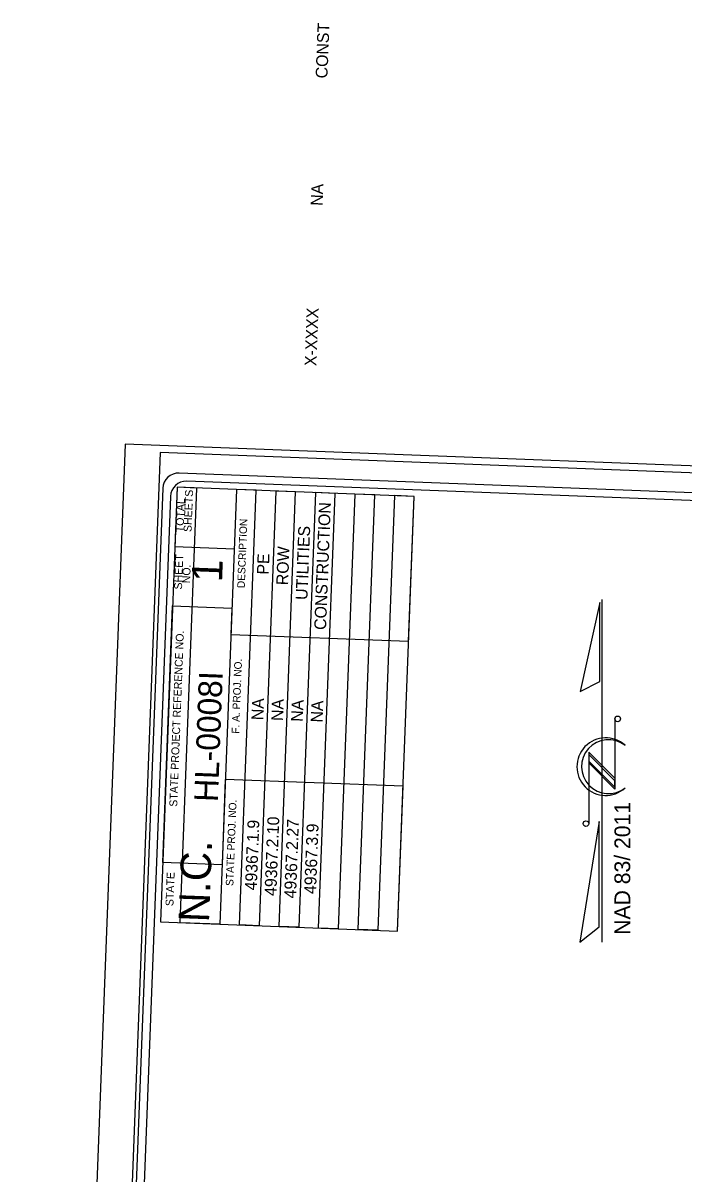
# Model space of a CAD drawing. Extents: x 2094564 to 2100382, y 679033 to 692366.
# Drawn here: x 2094564 to 2096651, y 688399 to 692034 of the extents above; entities that cross this region are included whole.
import ezdxf

# ---------------------------------------------------------------- set-up
doc = ezdxf.new("R2010")
doc.units = 0
for name, color, linetype in [('Old_Level_3', 7, 'Continuous'), ('Prop Horizontal Alignment Direction Label', 7, 'Continuous'), ('Prop Horizontal Alignment Tick Label', 7, 'Continuous'), ('Prop Horizontal Alignment Tick Large', 7, 'Continuous'), ('Scratch_Level_0', 7, 'Continuous')]:
    doc.layers.add(name, color=color, linetype=linetype)

msp = doc.modelspace()

# ---------------------------------------------------------------- linework, layer by layer
at = {"layer": 'Old_Level_3'}
for p, q in [((2096395, 689128.4), (2096395, 690211.8)), ((2096435.8, 689834.8), (2096435.8, 689612.4)), ((2096435.8, 689647.1), (2096353, 689729.9)), ((2096353, 689729.9), (2096353, 689503.9)), ((2096435.8, 689638.9), (2096353, 689721.8)), ((2096353, 689721.8), (2096353, 689701.4)), ((2096466.5, 689751.9), (2096467.6, 689751.1)), ((2096435.8, 689618.6), (2096353, 689701.4)), ((2096353, 689701.4), (2096435.8, 689618.6)), ((2096435.8, 689612.4), (2096353, 689695.3)), ((2096435.8, 689618.6), (2096435.8, 689638.9))]:
    msp.add_line(p, q, dxfattribs=at)
for points in [[(2096387.5, 690202.3), (2096325.6, 689920.9), (2096387.5, 689952.3)], [(2096386.1, 689510.1), (2096324.8, 689128.4), (2096386.1, 689176.8)]]:
    msp.add_lwpolyline(points, close=True, dxfattribs=at)
for centre in [(2096444.6, 689834.6), (2096344.1, 689503.6)]:
    msp.add_circle(centre, 8.83, dxfattribs=at)
for centre, radius, start, end in [((2096406.5, 689683.6), 91, 47.84, 312.3941), ((2096415.3, 689683.7), 85.3, 53.095, 308.6287)]:
    msp.add_arc(centre, radius, start, end, dxfattribs=at)
at = {"layer": 'Prop Horizontal Alignment Direction Label'}
for points in [[(2100204.3, 690414.1), (2095058.2, 690611.5)], [(2095006.3, 690563.5), (2094722.6, 683168.8)], [(2095748.1, 689164), (2095800.8, 690538), (2095738.4, 690540.3), (2095685.7, 689166.4), (2095623.3, 689168.7), (2095676, 690542.7), (2095613.5, 690545.1), (2095560.8, 689171.2), (2095498.3, 689173.5), (2095551, 690547.5), (2095488.6, 690549.9), (2095435.9, 689175.9), (2095373.5, 689178.3), (2095426.1, 690552.3), (2095363.7, 690554.7), (2095311, 689180.7), (2095248.6, 689183.1), (2095301.3, 690557.1), (2095238.7, 690559.5), (2095186, 689185.5), (2095061.1, 689190.3), (2095113.8, 690564.3), (2095051.4, 690566.7), (2094998.7, 689192.7), (2095748.1, 689164), (2095765.8, 689621.9), (2095203.7, 689643.4), (2095193.3, 689372.9), (2095005.9, 689380.1), (2095037.1, 690192), (2095224.4, 690184.8), (2095221.2, 690101.3), (2095783.3, 690079.8), (2095800.8, 690538), (2095051.4, 690566.7), (2095044.2, 690379.3), (2095231.6, 690372.2)], [(2099254.1, 690425.5), (2095082.1, 690585.5)], [(2095030.3, 690537.5), (2094758.2, 683442.8)]]:
    msp.add_lwpolyline(points, dxfattribs=at)
for centre in [(2095056, 690561.5), (2095080, 690535.6)]:
    msp.add_arc(centre, 50, 87.8037, 177.8037, dxfattribs=at)
at = {"layer": 'Prop Horizontal Alignment Tick Label'}
msp.add_lwpolyline([(2099950.1, 682147.8), (2100269.5, 690474.2), (2094997.8, 690676.3), (2094678.5, 682349.9)], close=True, dxfattribs=at)
at = {"layer": 'Prop Horizontal Alignment Tick Large'}
msp.add_lwpolyline([(2094886.5, 690703.1), (2094563.9, 682289.3), (2100059.8, 682078.5), (2100382.4, 690492.3)], close=True, dxfattribs=at)

# ---------------------------------------------------------------- texts
at = {"layer": 'Old_Level_3'}
msp.add_text('NAD 83/ 2011', height=50, rotation=90, dxfattribs=at).set_placement((2096484.1, 689152.1))
at = {"layer": 'Prop Horizontal Alignment Direction Label'}
for s, height, p in [('SHEETS', 25, (2095096.7, 690424.8)), ('TOTAL', 25, (2095071.7, 690424.1)), ('DESCRIPTION', 24, (2095265.1, 690247.5)), ('SHEET', 25, (2095066.5, 690243.1)), ('NO.', 25, (2095092, 690262.9)), ('1', 96.7, (2095193.2, 690265.3)), ('STATE PROJECT REFERENCE NO.', 24.999, (2095051.5, 689556.4)), ('F. A. PROJ. NO.', 24, (2095247.4, 689787.4)), ('STATE PROJ. NO.', 24, (2095228.9, 689306.2)), ('N.C.', 96.75, (2095152, 689190.6)), ('STATE', 25, (2095039.4, 689242.4))]:
    msp.add_text(s, height=height, rotation=87.8037, dxfattribs=at).set_placement(p)
at = {"layer": 'Scratch_Level_0'}
for s, height, p in [('CONST', 37.5, (2095526.5, 691858.6)), ('NA', 37.5, (2095511, 691455.9)), ('X-XXXX', 37.5, (2095491.6, 690949.3)), ('CONSTRUCTION', 37.5, (2095522.1, 690115.2)), ('UTILITIES', 37.5, (2095463.2, 690210)), ('ROW', 37.5, (2095402.1, 690256.5)), ('PE', 37.5, (2095340.8, 690290)), ('HL-0008I', 75, (2095179.9, 689571.1)), ('NA', 37.5, (2095323.6, 689829.8)), ('NA', 37.5, (2095386.1, 689827.4)), ('NA', 37.5, (2095448.5, 689825)), ('NA', 37.5, (2095511, 689822.6)), ('49367.1.9', 37.5, (2095303, 689291.8)), ('49367.2.10', 37.5, (2095364.9, 689274.3)), ('49367.2.27', 37.5, (2095427.1, 689266.5)), ('49367.3.9', 37.5, (2095490.2, 689280.1))]:
    msp.add_text(s, height=height, rotation=87.8037, dxfattribs=at).set_placement(p)

doc.saveas('drawing.dxf')
